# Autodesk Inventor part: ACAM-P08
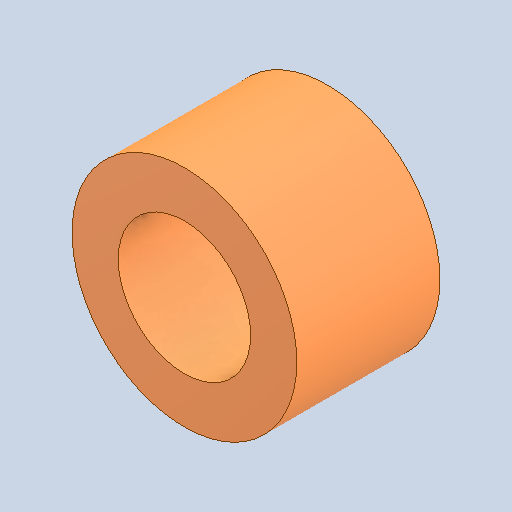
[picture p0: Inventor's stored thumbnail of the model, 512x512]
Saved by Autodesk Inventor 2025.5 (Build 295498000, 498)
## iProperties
Created: 2026-10
Part Number: ACAM-P08
Material: Genérico
Document SubType Name: Modeling
Designer: Luis M
Density: 1 g/cm^3
Appearance: Valor por defecto
Description: Centrador Ø15–M8
Material_BOM: PLA
Proceso_BOM: Impresión 3D
Author: Luis M
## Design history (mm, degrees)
feature "Base1"
node "Sólido1"
